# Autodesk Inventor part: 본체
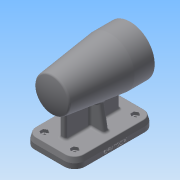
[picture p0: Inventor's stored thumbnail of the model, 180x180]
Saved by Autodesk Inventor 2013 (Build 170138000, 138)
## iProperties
Created: 2017-01
Part Number: 본체
Material: 일반
Document SubType Name: Modeling
Designer: Administrator
Density: 1 g/cm^3
Author: Administrator
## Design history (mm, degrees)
sketch "스케치3"
  geometry: L1 (56, 35)-(-56, 35); L2 (-56, 35)-(-56, -35); L3 (-56, -35)-(56, -35); L4 (56, -35)-(56, 35); L5 (56, 35)-(-56, -35); L6 (-56, 35)-(56, -35); 3 further points
  constraints: 12 end point, 3 midpoint, 2 parallel, 1 coincident, 1 horizontal, 1 perpendicular
  dimensions: "d0" = 112 distance of L2.end L3.end; "d2" = 70 distance of L1.end L2.end
extrude "돌출1" new body sketch "스케치3" distance "d3" = 14; taper "d4" = 0 deg
sketch "스케치4"
  geometry: L1 (56, 0)-(-56, 0) reference; L2 (56, 74)-(-56, 74); L3 (56, 74)-(56, 108); L4 (56, 108)-(28, 108); L5 (28, 108)-(-52.27, 98.144); A1 r 80 centre (24, 74) between (-52.27, 98.144) and (-56, 74); 3 further points
  constraints: 8 end point, 2 midpoint, 2 perpendicular, 2 point on circle, 1 centre point, 1 parallel, 1 point on line, 1 vertical alignment
  dimensions: "d5" = 74 distance from line of L2 point (0, 0); "d7" = 112 distance of L2.end L2.start; "d8" = 7 deg angle of L4 L5; "d9" = 28 distance of L3.end L4.end; "d10" = 68 diameter of L4 L2; "d12" = 160 diameter of A1
revolve "회전1" sketch "스케치4" stored, may be unused: angle "d14" = 90 deg
sketch "스케치5"
  geometry: L1 (56, 40)-(56, 108) reference; L2 (56, 74)-(-56, 74); L3 (56, 74)-(56, 95); L4 (56, 95)-(41, 95); L5 (41, 95)-(41, 98); L6 (41, 98)-(-13, 98); L7 (-13, 98)-(-13, 95); L8 (-13, 95)-(-25, 95); L9 (-25, 95)-(-25, 91.5); L10 (-25, 91.5)-(-43, 91.5); L11 (-43, 91.5)-(-43, 90); L12 (-43, 90)-(-47, 90); L13 (-47, 90)-(-47, 84.5); L14 (-47, 84.5)-(-50, 84.5); L15 (-50, 84.5)-(-50, 74); 2 further points
  constraints: 28 end point, 8 perpendicular, 3 parallel, 2 midpoint, 2 point on line, 1 collinear, 1 vertical
  dimensions: "d15" = 112 distance of L2.start L2.end; "d17" = 42 diameter of L4 L2; "d18" = 48 diameter of L6 L2; "d19" = 42 diameter of L8 L2; "d20" = 35 diameter of L10 L2; "d21" = 32 diameter of L12 L2; "d22" = 21 diameter of L14 L2; "d23" = 3 distance of L13.end L14.end; "d24" = 15 distance of L3.end L4.end; "d25" = 54 distance of L5.end L6.end; "d26" = 18 distance of L9.end L10.end; "d28" = 4 distance of L11.end L12.end; "d29" = 12 distance of L7.end L8.end
revolve "회전2" sketch "스케치5" stored, may be unused: angle "d30" = 90 deg
sketch "스케치6"
  geometry: L1 (-38, -4)-(38, -4); L2 (38, -4)-(38, 4); L3 (38, 4)-(-38, 4); L4 (-38, 4)-(-38, -4); L5 (-38, -4)-(38, 4); L6 (38, -4)-(-38, 4); L7 (-56, 35)-(-56, -35) reference; 3 further points
  constraints: 12 end point, 3 midpoint, 2 parallel, 1 coincident, 1 horizontal, 1 perpendicular
  dimensions: "d31" = 18 distance between parallel lines of L4 L7; "d32" = 8 distance of L3.end L1.start
extrude "돌출2" join sketch "스케치6" stored distance "d33" = 14; taper "d34" = 0 deg
sketch "스케치7"
  geometry: L1 (14, -35)-(14, 35) reference; L2 (49.169, 16.799)-(14, 23); L3 (14, 23)-(14, -23); L4 (14, -23)-(49.169, -16.799); L5 (0, 35)-(14, 35) reference; L6 (0, -35)-(14, -35) reference; L7 (49.169, 16.799)-(49.169, -16.799); 2 further points
  constraints: 8 end point, 1 collinear, 1 horizontal alignment, 1 midpoint, 1 perpendicular, 1 vertical
  dimensions: "d35" = 12 distance from line of L2.end L5; "d36" = 12 distance from line of L6 L3.end; "d37" = 100 deg angle of L2 L1; "d38" = 100 deg angle of L1 L4
extrude "돌출3" join sketch "스케치7" stored distance "d39" = 8; taper "d40" = 0 deg
fillet "모깎기1" dims "d41" = 14.5
sketch "스케치8"
  geometry: L1 (41.5, 35)-(-41.5, 35) reference; L2 (-56, 20.5)-(-56, -20.5) reference; L3 (-41.5, -35)-(41.5, -35) reference; L4 (56, -20.5)-(56, 20.5) reference; A1 r 14.5 centre (-41.5, 20.5) between (-41.5, 35) and (-56, 20.5) reference; A2 r 14.5 centre (-41.5, -20.5) between (-56, -20.5) and (-41.5, -35) reference; A3 r 14.5 centre (41.5, -20.5) between (41.5, -35) and (56, -20.5) reference; A4 r 14.5 centre (41.5, 20.5) between (56, 20.5) and (41.5, 35) reference; 1 further point
extrude "돌출4" cut sketch "스케치8" distance "d42" = 7; taper "d43" = 0 deg
sketch "스케치9"
  geometry: L1 (56, -20.5)-(56, 20.5) reference; L2 (-41.5, -35)-(41.5, -35) reference; L3 (-56, 20.5)-(-56, -20.5) reference; L4 (41.5, 35)-(-41.5, 35) reference; A1 r 14.5 centre (41.5, 20.5) between (56, 20.5) and (41.5, 35) reference; A2 r 14.5 centre (41.5, -20.5) between (41.5, -35) and (56, -20.5) reference; A3 r 14.5 centre (-41.5, -20.5) between (-56, -20.5) and (-41.5, -35) reference; A4 r 14.5 centre (-41.5, 20.5) between (-41.5, 35) and (-56, 20.5) reference; 1 further point
extrude "돌출5" join sketch "스케치9" distance "d44" = 7; taper "d45" = -15 deg
fillet "모깎기2" dims "d46" = 1
fillet "모깎기3" dims "d47" = 0.3
fillet "모깎기4" dims "d48" = 3
fillet "모깎기5" dims "d49" = 3
chamfer "모따기1" distance "d50" = 1; stored, may be unused: second distance "d51" = 2, angle "d52" = 45 deg
fillet "모깎기6" dims "d53" = 3
fillet "모깎기7" dims "d54" = 3
fillet "모깎기8" dims "d55" = 3
sketch "스케치10"
  geometry: C1 r 34 at (0, 0) reference; 2 further points
  constraints: 1 vertical alignment
  dimensions: "d56" = 26 distance of point (0, 26) C1.centre
hole "구멍1" sketch "스케치10" at (0, 26) diameter "d57" = 3.242; stored, may be unused: countersink angle "d61" = 90 deg, drill point angle "d63" = 118 deg; dims "d58" = 8, "d59" = 4, "d60" = 2, "d62" = 11
sketch "스케치11" dims "d72" = 10
  geometry: L1 (-41.5, 35)-(41.5, 35) reference; L2 (-56, -20.5)-(-56, 20.5) reference; L3 (-37, 21)-(-39.5, 16.67); L4 (-39.5, 16.67)-(-44.5, 16.67); L5 (-44.5, 16.67)-(-47, 21); L6 (-47, 21)-(-44.5, 25.33); L7 (-44.5, 25.33)-(-39.5, 25.33); L8 (-39.5, 25.33)-(-37, 21); 4 further points
  constraints: 12 end point, 2 coincident, 1 horizontal alignment, 15 other
  dimensions: "d70" = 14 distance from line of point (-42, 21) L1; "d71" = 14 distance from line of point (-42, 21) L2; "d73" = 4.33013 vertical distance of L7.end L3.start
extrude "돌출6" cut sketch "스케치11" distance "d77" = 4; taper "d78" = 0 deg
sketch "스케치12"
  geometry: L1 (-44.5, -25.33)-(-39.5, -25.33) reference; L2 (-39.5, -25.33)-(-37, -21) reference; L3 (-37, -21)-(-39.5, -16.67) reference; L4 (-39.5, -16.67)-(-44.5, -16.67) reference; L5 (-44.5, -16.67)-(-47, -21) reference; L6 (-47, -21)-(-44.5, -25.33) reference; L7 (-47, -21)-(-37, -21); L8 (-39.5, -25.33)-(-44.5, -16.67); L9 (-44.5, -25.33)-(-39.5, -16.67); 2 further points
  constraints: 6 end point, 2 parallel, 1 midpoint
hole "구멍2" sketch "스케치12" at (-42, -21) diameter "d79" = 5; stored, may be unused: countersink angle "d83" = 90 deg, drill point angle "d85" = 118 deg; dims "d80" = 8, "d81" = 4, "d82" = 2, "d84" = 15
sketch "스케치13"
  geometry: L1 (97.5, 0)-(97.5, 7) reference; 2 further points
  constraints: 1 other
  dimensions: "d89" = 4 distance of point (41.5, 0) point (41.5, 4); "d90" = 56 distance from line of L1 point (41.5, 4)
feature "엠보싱1" sketch "스케치13" dims "d0" = 112, "d2" = 70, "d91" = 0.5, "d92" = 0
fillet "모깎기9" dims "d93" = 3
node "솔리드1"
pattern_circular "원형 패턴1" dims angle "d65" = 360 deg
pattern_linear "직사각형 패턴1" dims "d88" = 42
mirror "대칭1"
mirror "대칭2"
node "투영된 루프1"
